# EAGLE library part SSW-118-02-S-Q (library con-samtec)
THROUGH-HOLE .025" SQ POST SOCKET Source: Samtec SSW.pdf
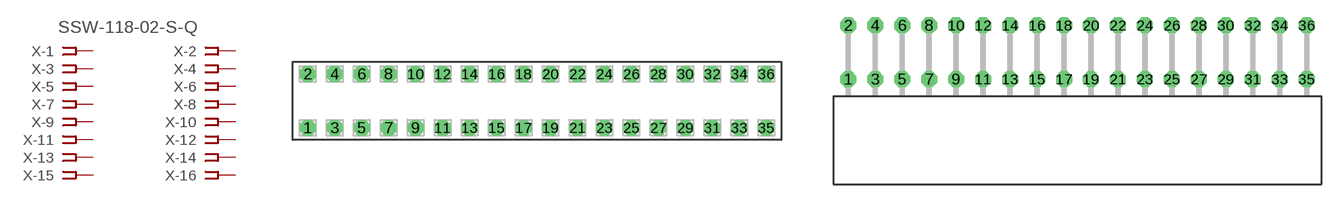
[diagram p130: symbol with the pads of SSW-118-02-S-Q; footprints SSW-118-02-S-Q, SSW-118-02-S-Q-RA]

Designator prefix X; gates -1=FPINV -2=FPIN -3=FPIN -4=FPIN -5=FPIN -6=FPIN -7=FPIN -8=FPIN -9=FPIN -10=FPIN -11=FPIN -12=FPIN -13=FPIN -14=FPIN -15=FPIN -16=FPIN -17=FPIN -18=FPIN -19=FPIN -20=FPIN -21=FPIN -22=FPIN -23=FPIN -24=FPIN -25=FPIN -26=FPIN -27=FPIN -28=FPIN -29=FPIN -30=FPIN -31=FPIN -32=FPIN -33=FPIN -34=FPIN -35=FPIN -36=FPIN

## SSW-118-02-S-Q (MPN: SSW-118-02-S-Q; OC_FARNELL: unknown; OC_NEWARK: 82P7801)  [SSW-118-02-S-Q]
1  -1:1  pas
2  -2:1  pas
3  -3:1  pas
4  -4:1  pas
5  -5:1  pas
6  -6:1  pas
7  -7:1  pas
8  -8:1  pas
9  -9:1  pas
10  -10:1  pas
11  -11:1  pas
12  -12:1  pas
13  -13:1  pas
14  -14:1  pas
15  -15:1  pas
16  -16:1  pas
17  -17:1  pas
18  -18:1  pas
19  -19:1  pas
20  -20:1  pas
21  -21:1  pas
22  -22:1  pas
23  -23:1  pas
24  -24:1  pas
25  -25:1  pas
26  -26:1  pas
27  -27:1  pas
28  -28:1  pas
29  -29:1  pas
30  -30:1  pas
31  -31:1  pas
32  -32:1  pas
33  -33:1  pas
34  -34:1  pas
35  -35:1  pas
36  -36:1  pas

## SSW-118-02-S-QRA (MPN: SSW-118-02-S-Q-RA; OC_FARNELL: unknown; OC_NEWARK: 82P7802)  [SSW-118-02-S-Q-RA]
Pads as for SSW-118-02-S-Q

## Footprint SSW-118-02-S-Q (pad centres in mm)
THROUGH-HOLE .025" SQ POST SOCKET Source: Samtec SSW.pdf
drill 1 pad 1.5 octagon: 1 -21.59,-2.54; 2 -21.59,2.54; 3 -19.05,-2.54; 4 -19.05,2.54; 5 -16.51,-2.54; 6 -16.51,2.54; 7 -13.97,-2.54; 8 -13.97,2.54; 9 -11.43,-2.54; 10 -11.43,2.54; 11 -8.89,-2.54; 12 -8.89,2.54; 13 -6.35,-2.54; 14 -6.35,2.54; 15 -3.81,-2.54; 16 -3.81,2.54; 17 -1.27,-2.54; 18 -1.27,2.54; 19 1.27,-2.54; 20 1.27,2.54; 21 3.81,-2.54; 22 3.81,2.54; 23 6.35,-2.54; 24 6.35,2.54; 25 8.89,-2.54; 26 8.89,2.54; 27 11.43,-2.54; 28 11.43,2.54; 29 13.97,-2.54; 30 13.97,2.54; 31 16.51,-2.54; 32 16.51,2.54; 33 19.05,-2.54; 34 19.05,2.54; 35 21.59,-2.54; 36 21.59,2.54

## Footprint SSW-118-02-S-Q-RA (pad centres in mm)
THROUGH-HOLE .025" SQ POST SOCKET Source: Samtec SSW.pdf
drill 1 pad 1.5 octagon: 1 -21.59,1.524; 2 -21.59,6.604; 3 -19.05,1.524; 4 -19.05,6.604; 5 -16.51,1.524; 6 -16.51,6.604; 7 -13.97,1.524; 8 -13.97,6.604; 9 -11.43,1.524; 10 -11.43,6.604; 11 -8.89,1.524; 12 -8.89,6.604; 13 -6.35,1.524; 14 -6.35,6.604; 15 -3.81,1.524; 16 -3.81,6.604; 17 -1.27,1.524; 18 -1.27,6.604; 19 1.27,1.524; 20 1.27,6.604; 21 3.81,1.524; 22 3.81,6.604; 23 6.35,1.524; 24 6.35,6.604; 25 8.89,1.524; 26 8.89,6.604; 27 11.43,1.524; 28 11.43,6.604; 29 13.97,1.524; 30 13.97,6.604; 31 16.51,1.524; 32 16.51,6.604; 33 19.05,1.524; 34 19.05,6.604; 35 21.59,1.524; 36 21.59,6.604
